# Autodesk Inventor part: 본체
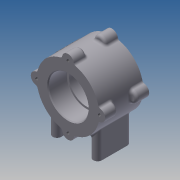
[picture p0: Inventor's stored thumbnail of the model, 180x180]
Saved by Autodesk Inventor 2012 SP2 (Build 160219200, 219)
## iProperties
Created: 2015-03
Part Number: 본체
Material: 알루미늄-6061
Document SubType Name: Modeling
Designer: Administrator
Density: 2.71 g/cm^3
Mass: 450.336 g
Surface Area: 333.336 cm^2
Volume: 166.176 cm^3
Author: Administrator
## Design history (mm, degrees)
sketch "스케치1"
  geometry: C1 r 37 at (0, 0); 1 further point
  constraints: 1 centre point, 1 coincident
  dimensions: "d0" = 74 diameter of C1
extrude "돌출1" new body sketch "스케치1" distance "d1" = 26; taper "d3" = 0 deg; dims "d2" = 26, "d4" = 0
sketch "스케치2"
  geometry: A1 r 37 centre (0, 0) between (0, 37) and (-6.969, 36.338) reference; A2 r 7 centre (0, 37) between (6.969, 36.338) and (-6.969, 36.338)
  constraints: 5 point on circle, 1 centre point, 1 coincident, 1 vertical alignment
  dimensions: "d5" = 14 diameter of A2
extrude "돌출2" join sketch "스케치2" distance "d6" = 15; taper "d7" = 0 deg
fillet "모깎기1" dims "d8" = 3
sketch "스케치3"
  geometry: A1 r 37 centre (0, 0) between (35.863, 9.104) and (9.104, 35.863) reference; 1 further point
  constraints: 1 coincident
hole "구멍1" sketch "스케치3" at (0, 0) diameter "d12" = 47; stored, may be unused: countersink angle "d16" = 90 deg, drill point angle "d18" = 0 deg; dims "d13" = 6, "d14" = 4, "d15" = 2, "d17" = 22
sketch "스케치4"
  geometry: C1 r 23.5 at (0, 0) reference; 1 further point
  constraints: 1 coincident
hole "구멍2" sketch "스케치4" at (0, 0) diameter "d19" = 42; stored, may be unused: countersink angle "d23" = 90 deg, drill point angle "d25" = 0 deg; dims "d20" = 6, "d21" = 4, "d22" = 2, "d24" = 22
node "작업 평면2"
sketch "스케치5"
  geometry: L1 (-6.889, 26)-(6.889, 26) reference; L2 (-6.889, -26)-(6.889, -26) reference; L3 (35.863, -26)-(9.104, -26) reference; L4 (-9.104, -26)-(-35.863, -26) reference; L5 (-35.863, 26)-(-9.104, 26) reference; L6 (9.104, 26)-(35.863, 26) reference; L7 (37, -11)-(37, 11) reference; L8 (-37, -11)-(-37, 11) reference; L9 (0, 26)-(0, -26); L10 (-37, 0)-(37, 0); L11 (19, -15)-(19, 15); L12 (29, -15)-(29, 15); L13 (-19, -15)-(-19, 15); L14 (-29, -15)-(-29, 15); A1 r 5 centre (24, -15) between (19, -15) and (29, -15); A2 r 5 centre (24, 15) between (29, 15) and (19, 15); A3 r 5 centre (-24, -15) between (-29, -15) and (-19, -15); A4 r 5 centre (-24, 15) between (-19, 15) and (-29, 15); 2 further points
  constraints: 12 end point, 8 point on circle, 6 symmetric about line, 4 centre point, 4 midpoint, 2 tangent, 1 coincident, 1 parallel, 1 perpendicular, 1 vertical alignment, 2 other
  dimensions: "d28" = 24 distance from line of point (24, -15) L9; "d29" = 15 distance from line of L10 point (24, -15); "d30" = 10 diameter of A1; "d31" = 10 diameter of A2; "d32" = 30 distance of A2.centre A1.centre
extrude "돌출3" join sketch "스케치5" stored distance "d33" = 15; taper "d34" = 0 deg
sketch "스케치6"
  geometry: A1 r 7 centre (0, 37) between (6.889, 38.239) and (-6.889, 38.239) reference; 1 further point
  constraints: 1 coincident
hole "구멍3" sketch "스케치6" at (0, 37) diameter "d35" = 3.459; stored, may be unused: countersink angle "d39" = 90 deg, drill point angle "d41" = 118 deg; dims "d36" = 8, "d37" = 4, "d38" = 2, "d40" = 11
sketch "스케치7"
  geometry: A1 r 7 centre (0, -37) between (-6.889, -38.239) and (6.889, -38.239) reference; 1 further point
  constraints: 1 coincident
hole "구멍4" sketch "스케치7" at (0, -37) diameter "d45" = 3.459; stored, may be unused: countersink angle "d49" = 90 deg, drill point angle "d51" = 118 deg; dims "d46" = 8, "d47" = 4, "d48" = 2, "d50" = 11
sketch "스케치8"
  geometry: A1 r 5 centre (-24, -15) between (-29, -15) and (-19, -15) reference; A2 r 5 centre (-24, 15) between (-19, 15) and (-29, 15) reference; 3 further points
  constraints: 2 coincident
hole "구멍5" sketch "스케치8" at (-24, 15), (-24, -15) diameter "d55" = 4.459; stored, may be unused: countersink angle "d59" = 90 deg, drill point angle "d61" = 118 deg; dims "d56" = 6, "d57" = 4, "d58" = 2, "d60" = 8
fillet "모깎기2" dims "d62" = 0.3
chamfer "모따기1" distance "d63" = 1; stored, may be unused: second distance "d64" = 2, angle "d65" = 45 deg
fillet "모깎기3" dims "d66" = 3
fillet "모깎기4" dims "d67" = 3
sketch "스케치10"
  geometry: L1 (0, 0)-(24.5, 0); L2 (0, 0)-(26.163, 26.163); L3 (24.335, 27.871)-(24.466, 28.001); L4 (24.466, 28.001)-(28.001, 24.466); L5 (28.001, 24.466)-(27.871, 24.335); A1 r 37 centre (0, 0) between (35.863, 9.104) and (9.104, 35.863) reference; 1 further point
  constraints: 10 end point, 3 point on circle, 2 parallel, 1 horizontal, 1 horizontal alignment, 1 perpendicular, 2 other
  dimensions: "d68" = 45 deg angle of L2 L1; "d69" = 0.1 distance from line of L4 L2.end; "d70" = 5 distance of L3.end L4.end
extrude "돌출4" join sketch "스케치10" distance "d71" = 26; taper "d73" = 0 deg; dims "d72" = 26, "d74" = 0
sketch "스케치11"
  geometry: L1 (5, 52)-(0, 52) reference; L2 (0, 0)-(5, 0) reference; L3 (0, 39)-(0, 13); L4 (0, 13)-(5, 13); L5 (5, 13)-(5, 39); L6 (5, 39)-(0, 39); 3 further points
  constraints: 2 midpoint, 1 horizontal, 1 vertical alignment, 2 other
  dimensions: "d75" = 5 distance of L5.end L3.start; "d76" = 26 distance of L4.end L5.end; "d78" = 13 distance between parallel lines of L2 L4
feature "엠보싱1" sketch "스케치11" dims "d79" = 0.4, "d80" = 0
node "솔리드1"
pattern_circular "원형 패턴1" dims angle "d10" = 360 deg
mirror "대칭2"
mirror "대칭3"
pattern_circular "원형 패턴2" dims angle "d43" = 360 deg
pattern_circular "원형 패턴3" dims angle "d53" = 360 deg
mirror "대칭4"
other parameters: "d27" = -56
